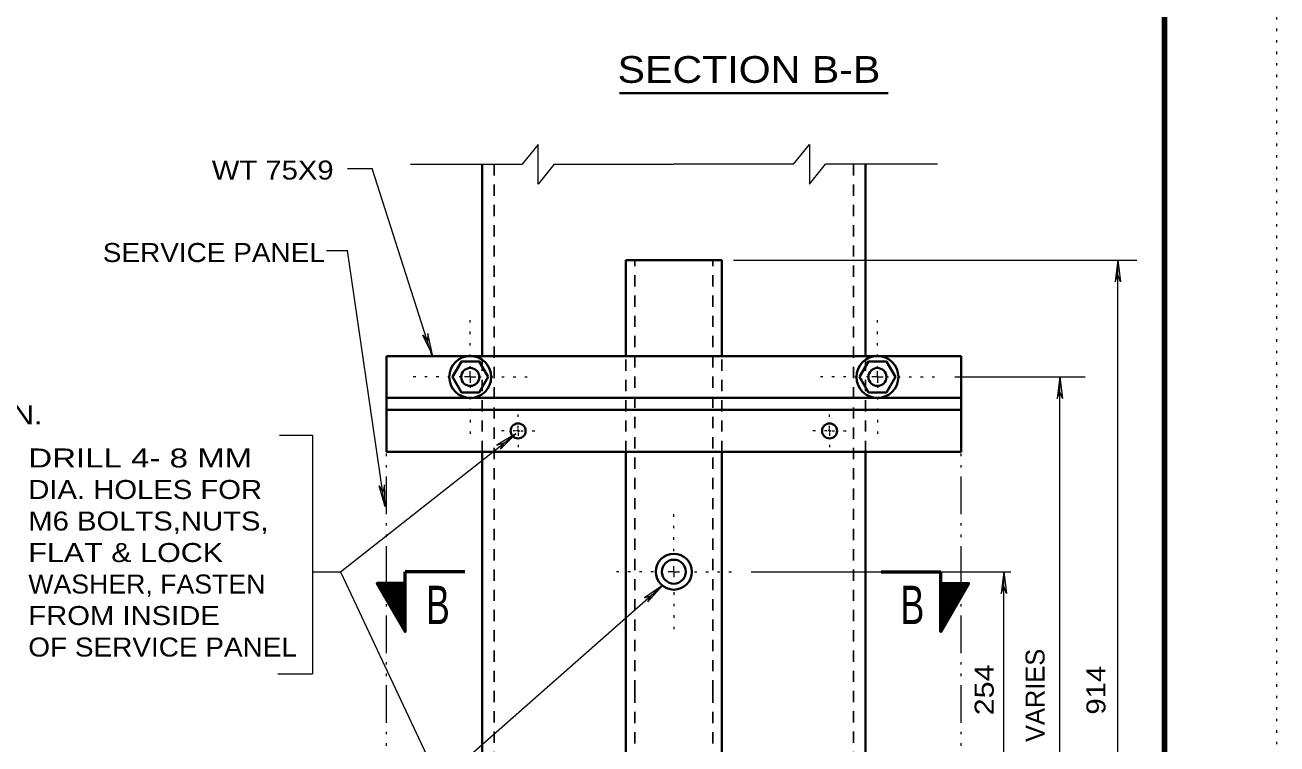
# Model space of a CAD drawing. Extents: x 312583 to 312854, y 144419 to 144597.
# Drawn here: x 312803.4 to 312853.5, y 144478.4 to 144507.1 of the extents above; entities that cross this region are included whole.
import ezdxf
from ezdxf.enums import TextEntityAlignment as Align

# ---------------------------------------------------------------- set-up
doc = ezdxf.new("R2010")
doc.units = 0
doc.header["$LTSCALE"] = 0.3
for name, pattern in [('DASH_DOUBLE_DOT', [9.2, 5, -1.2, 0.3, -1.2, 0.3, -1.2]), ('DOTTED', [1.5, 0.3, -1.2]), ('SHORT_DASHED', [2.7, 1.5, -1.2])]:
    doc.linetypes.add(name, pattern=pattern)
doc.layers.add('1', color=7, linetype='Continuous', lineweight=13)
doc.layers.add('63', color=7, linetype='DOTTED', lineweight=13)

msp = doc.modelspace()

# ---------------------------------------------------------------- linework, layer by layer
at = {"layer": '1', "lineweight": 158}
msp.add_line((312849, 144423.1446), (312849, 144585.0846), dxfattribs=at)
at = {"layer": '1', "lineweight": 35}
for p, q in [((312827.1926, 144504.4241), (312837.9474, 144504.4241)), ((312817.5353, 144484.8097), (312817.5199, 144484.7943)), ((312817.5813, 144484.8097), (312817.5276, 144484.7713)), ((312817.6349, 144484.8097), (312817.5429, 144484.756)), ((312817.6809, 144484.8097), (312817.5583, 144484.733)), ((312817.7346, 144484.8097), (312817.5659, 144484.71)), ((312817.7729, 144484.8097), (312817.5813, 144484.6947)), ((312817.8266, 144484.8097), (312817.5889, 144484.6717)), ((312817.8726, 144484.8097), (312817.6043, 144484.6487)), ((312817.9186, 144484.8097), (312817.6119, 144484.6333)), ((312817.9646, 144484.8097), (312817.6273, 144484.6027)), ((312818.0183, 144484.8097), (312817.6349, 144484.5873)), ((312818.0643, 144484.8097), (312817.6503, 144484.5643)), ((312818.1103, 144484.8097), (312817.6579, 144484.5413)), ((312818.1639, 144484.8097), (312817.6733, 144484.526)), ((312818.2099, 144484.8097), (312817.6809, 144484.503)), ((312818.2559, 144484.8097), (312817.6963, 144484.4877)), ((312818.3096, 144484.8097), (312817.7116, 144484.4647)), ((312818.3556, 144484.8097), (312817.7193, 144484.4417)), ((312818.4016, 144484.8097), (312817.7346, 144484.4263)), ((312818.4476, 144484.8097), (312817.7499, 144484.4033)), ((312818.5013, 144484.8097), (312817.7576, 144484.3803)), ((312818.5396, 144484.8097), (312817.7729, 144484.365)), ((312818.5933, 144484.8097), (312817.7806, 144484.3343)), ((312818.6163, 144484.7943), (312817.7959, 144484.319)), ((312818.6163, 144484.7637), (312817.8036, 144484.296)), ((312818.6163, 144484.733), (312817.8189, 144484.273)), ((312818.6163, 144484.71), (312817.8266, 144484.2577)), ((312818.6163, 144484.6793), (312817.8419, 144484.2347)), ((312818.6086, 144484.6563), (312817.8496, 144484.2117)), ((312818.6086, 144484.6257), (312817.8649, 144484.1963)), ((312818.6163, 144484.6027), (312817.8726, 144484.1733)), ((312818.6163, 144484.572), (312817.8879, 144484.1503)), ((312818.6163, 144484.5413), (312817.9033, 144484.135)), ((312818.6163, 144484.5183), (312817.9109, 144484.112)), ((312818.6163, 144484.4877), (312817.9263, 144484.089)), ((312818.6163, 144484.457), (312817.9416, 144484.066)), ((312818.6163, 144484.434), (312817.9493, 144484.0507)), ((312818.6086, 144484.4033), (312817.9646, 144484.0277)), ((312818.6163, 144484.3727), (312817.9723, 144484.0047)), ((312840.0523, 144484.7943), (312840.8726, 144484.319)), ((312840.0523, 144484.7637), (312840.8649, 144484.296)), ((312840.0523, 144484.733), (312840.8496, 144484.273)), ((312840.0523, 144484.71), (312840.8419, 144484.2577)), ((312840.0523, 144484.6793), (312840.8266, 144484.2347)), ((312840.0523, 144484.6027), (312840.7959, 144484.1733)), ((312840.0523, 144484.572), (312840.7806, 144484.1503)), ((312840.0523, 144484.5413), (312840.7653, 144484.135)), ((312840.0523, 144484.5183), (312840.7576, 144484.112)), ((312840.0523, 144484.4877), (312840.7423, 144484.089)), ((312840.0523, 144484.457), (312840.7269, 144484.066)), ((312840.0523, 144484.434), (312840.7193, 144484.0507)), ((312840.0523, 144484.3727), (312840.6963, 144484.0047)), ((312840.0599, 144484.6563), (312840.8189, 144484.2117)), ((312840.0599, 144484.6257), (312840.8036, 144484.1963)), ((312840.0599, 144484.4033), (312840.7039, 144484.0277)), ((312840.0753, 144484.8097), (312840.8879, 144484.3343)), ((312840.1289, 144484.8097), (312840.8956, 144484.365)), ((312840.1673, 144484.8097), (312840.9109, 144484.3803)), ((312840.2209, 144484.8097), (312840.9186, 144484.4033)), ((312840.2669, 144484.8097), (312840.9339, 144484.4263)), ((312840.3129, 144484.8097), (312840.9493, 144484.4417)), ((312840.3589, 144484.8097), (312840.9569, 144484.4647)), ((312840.4126, 144484.8097), (312840.9723, 144484.4877)), ((312840.4586, 144484.8097), (312840.9876, 144484.503)), ((312840.5046, 144484.8097), (312840.9953, 144484.526)), ((312840.5583, 144484.8097), (312841.0106, 144484.5413)), ((312840.6043, 144484.8097), (312841.0183, 144484.5643)), ((312840.6503, 144484.8097), (312841.0336, 144484.5873)), ((312840.7039, 144484.8097), (312841.0413, 144484.6027)), ((312840.7499, 144484.8097), (312841.0566, 144484.6333)), ((312840.7959, 144484.8097), (312841.0643, 144484.6487)), ((312840.8419, 144484.8097), (312841.0796, 144484.6717)), ((312840.8956, 144484.8097), (312841.0873, 144484.6947)), ((312840.9339, 144484.8097), (312841.1026, 144484.71)), ((312840.9876, 144484.8097), (312841.1103, 144484.733)), ((312841.0336, 144484.8097), (312841.1256, 144484.756)), ((312841.0873, 144484.8097), (312841.1409, 144484.7713)), ((312841.1333, 144484.8097), (312841.1486, 144484.7943)), ((312818.6163, 144484.3497), (312817.9876, 144483.9893)), ((312818.6163, 144484.3267), (312817.9953, 144483.9663)), ((312818.6163, 144484.296), (312818.0106, 144483.9433)), ((312818.6163, 144484.2653), (312818.0183, 144483.928)), ((312818.6163, 144484.2347), (312818.0336, 144483.905)), ((312818.6163, 144484.2117), (312818.0413, 144483.882)), ((312818.6163, 144484.181), (312818.0566, 144483.8667)), ((312818.6086, 144484.158), (312818.0643, 144483.836)), ((312818.6163, 144484.1273), (312818.0796, 144483.8207)), ((312818.6163, 144484.1043), (312818.0949, 144483.7977)), ((312818.6163, 144484.0737), (312818.1026, 144483.7747)), ((312818.6163, 144484.043), (312818.1179, 144483.7593)), ((312818.6163, 144484.02), (312818.1256, 144483.7363)), ((312818.6163, 144483.9893), (312818.1409, 144483.7133)), ((312818.6163, 144483.9587), (312818.1486, 144483.698)), ((312818.6163, 144483.9357), (312818.1639, 144483.675)), ((312818.6163, 144483.905), (312818.1716, 144483.652)), ((312818.6163, 144483.8743), (312818.1869, 144483.6367)), ((312840.0523, 144484.3497), (312840.6809, 144483.9893)), ((312840.0523, 144484.3267), (312840.6733, 144483.9663)), ((312840.0523, 144484.296), (312840.6579, 144483.9433)), ((312840.0523, 144484.2653), (312840.6503, 144483.928)), ((312840.0523, 144484.2347), (312840.6349, 144483.905)), ((312840.0523, 144484.2117), (312840.6273, 144483.882)), ((312840.0523, 144484.181), (312840.6119, 144483.8667)), ((312840.0523, 144484.1273), (312840.5889, 144483.8207)), ((312840.0523, 144484.1043), (312840.5736, 144483.7977)), ((312840.0523, 144484.0737), (312840.5659, 144483.7747)), ((312840.0523, 144484.043), (312840.5506, 144483.7593)), ((312840.0523, 144484.02), (312840.5429, 144483.7363)), ((312840.0523, 144483.9893), (312840.5276, 144483.7133)), ((312840.0523, 144483.9587), (312840.5199, 144483.698)), ((312840.0523, 144483.9357), (312840.5046, 144483.675)), ((312840.0523, 144483.905), (312840.4969, 144483.652)), ((312840.0523, 144483.8743), (312840.4816, 144483.6367)), ((312840.0599, 144484.158), (312840.6043, 144483.836)), ((312818.6163, 144483.8513), (312818.1946, 144483.6137)), ((312818.6163, 144483.8283), (312818.2099, 144483.5907)), ((312818.6163, 144483.7977), (312818.2176, 144483.5677)), ((312818.6163, 144483.767), (312818.2329, 144483.5523)), ((312818.6163, 144483.7363), (312818.2483, 144483.5293)), ((312818.6163, 144483.7133), (312818.2559, 144483.5063)), ((312818.6163, 144483.6827), (312818.2713, 144483.491)), ((312818.6163, 144483.6597), (312818.2866, 144483.468)), ((312818.6163, 144483.629), (312818.2943, 144483.445)), ((312818.6163, 144483.606), (312818.3096, 144483.4297)), ((312818.6163, 144483.5753), (312818.3173, 144483.4067)), ((312818.6163, 144483.5447), (312818.3326, 144483.3837)), ((312818.6163, 144483.5217), (312818.3403, 144483.3683)), ((312818.6163, 144483.491), (312818.3556, 144483.3377)), ((312818.6163, 144483.468), (312818.3633, 144483.3223)), ((312818.6163, 144483.4373), (312818.3786, 144483.2993)), ((312818.6163, 144483.4067), (312818.3863, 144483.2763)), ((312818.6163, 144483.3837), (312818.4016, 144483.261)), ((312840.0523, 144483.8513), (312840.4739, 144483.6137)), ((312840.0523, 144483.8283), (312840.4586, 144483.5907)), ((312840.0523, 144483.7977), (312840.4509, 144483.5677)), ((312840.0523, 144483.767), (312840.4356, 144483.5523)), ((312840.0523, 144483.7363), (312840.4203, 144483.5293)), ((312840.0523, 144483.7133), (312840.4126, 144483.5063)), ((312840.0523, 144483.6827), (312840.3973, 144483.491)), ((312840.0523, 144483.6597), (312840.3819, 144483.468)), ((312840.0523, 144483.629), (312840.3743, 144483.445)), ((312840.0523, 144483.606), (312840.3589, 144483.4297)), ((312840.0523, 144483.5753), (312840.3513, 144483.4067)), ((312840.0523, 144483.5447), (312840.3359, 144483.3837)), ((312840.0523, 144483.5217), (312840.3283, 144483.3683)), ((312840.0523, 144483.491), (312840.3129, 144483.3377)), ((312840.0523, 144483.468), (312840.3053, 144483.3223)), ((312840.0523, 144483.4373), (312840.2899, 144483.2993)), ((312840.0523, 144483.4067), (312840.2823, 144483.2763)), ((312840.0523, 144483.3837), (312840.2669, 144483.261)), ((312818.6163, 144483.353), (312818.4093, 144483.238)), ((312818.6163, 144483.33), (312818.4246, 144483.215)), ((312818.6163, 144483.2993), (312818.4399, 144483.1997)), ((312818.6163, 144483.2687), (312818.4476, 144483.1767)), ((312818.6163, 144483.238), (312818.4629, 144483.1537)), ((312818.6163, 144483.215), (312818.4783, 144483.1383)), ((312818.6163, 144483.1843), (312818.4859, 144483.1153)), ((312818.6163, 144483.1613), (312818.5013, 144483.0923)), ((312818.6163, 144483.1383), (312818.5089, 144483.0693)), ((312818.6163, 144483.1077), (312818.5243, 144483.054)), ((312818.6163, 144483.077), (312818.5319, 144483.031)), ((312818.6163, 144483.0463), (312818.5473, 144483.008)), ((312818.6163, 144483.0233), (312818.5549, 144482.9927)), ((312818.6163, 144482.9927), (312818.5703, 144482.9697)), ((312818.6163, 144482.9697), (312818.5779, 144482.9467)), ((312818.6163, 144482.939), (312818.5933, 144482.9313)), ((312818.6163, 144482.9083), (312818.6009, 144482.9083)), ((312840.0523, 144483.353), (312840.2593, 144483.238)), ((312840.0523, 144483.33), (312840.2439, 144483.215)), ((312840.0523, 144483.2993), (312840.2286, 144483.1997)), ((312840.0523, 144483.2687), (312840.2209, 144483.1767)), ((312840.0523, 144483.238), (312840.2056, 144483.1537)), ((312840.0523, 144483.215), (312840.1903, 144483.1383)), ((312840.0523, 144483.1843), (312840.1826, 144483.1153)), ((312840.0523, 144483.1613), (312840.1673, 144483.0923)), ((312840.0523, 144483.1383), (312840.1596, 144483.0693)), ((312840.0523, 144483.1077), (312840.1443, 144483.054)), ((312840.0523, 144483.077), (312840.1366, 144483.031)), ((312840.0523, 144483.0463), (312840.1213, 144483.008)), ((312840.0523, 144483.0233), (312840.1136, 144482.9927)), ((312840.0523, 144482.9927), (312840.0983, 144482.9697)), ((312840.0523, 144482.9697), (312840.0906, 144482.9467)), ((312840.0523, 144482.939), (312840.0753, 144482.9313)), ((312840.0523, 144482.9083), (312840.0676, 144482.9083))]:
    msp.add_line(p, q, dxfattribs=at)
at = {"layer": '1'}
for p, q in [((312816.3208, 144501.4089), (312817.3027, 144501.4089)), ((312819.6973, 144493.91), (312817.3027, 144501.4089)), ((312818.8309, 144501.5767), (312823.3006, 144501.5767)), ((312824.5809, 144501.5767), (312829.3726, 144501.5767)), ((312834.1643, 144501.5767), (312829.3726, 144501.5767)), ((312839.9143, 144501.5767), (312835.4446, 144501.5767)), ((312815.4739, 144498.1279), (312816.3206, 144498.1279)), ((312817.8036, 144487.8993), (312816.3206, 144498.1279)), ((312847.1303, 144497.7433), (312847.023, 144496.877)), ((312847.1303, 144463.2433), (312847.1303, 144497.7433)), ((312847.1303, 144497.7433), (312847.2377, 144496.877)), ((312847.023, 144496.877), (312847.1303, 144497.153)), ((312847.2377, 144496.877), (312847.1303, 144497.153)), ((312819.3273, 144494.7409), (312819.5192, 144494.517)), ((312819.7101, 144493.9556), (312819.3273, 144494.7409)), ((312819.5277, 144494.8103), (312819.5192, 144494.517)), ((312819.7101, 144493.9556), (312819.5277, 144494.8103)), ((312821.2229, 144493.0743), (312821.0006, 144493.0743)), ((312821.2229, 144493.0743), (312821.2229, 144493.3043)), ((312821.2229, 144493.0743), (312821.4529, 144493.0743)), ((312821.2229, 144493.0743), (312821.2229, 144492.8443)), ((312837.5146, 144493.0743), (312837.2923, 144493.0743)), ((312837.5146, 144493.0743), (312837.5146, 144493.3043)), ((312837.5146, 144493.0743), (312837.5146, 144492.8443)), ((312837.5146, 144493.0743), (312837.7446, 144493.0743)), ((312844.8088, 144493.0743), (312844.7015, 144492.208)), ((312844.8088, 144467.92), (312844.8088, 144493.0743)), ((312844.8088, 144493.0743), (312844.9162, 144492.208)), ((312844.7015, 144492.208), (312844.8088, 144492.484)), ((312844.9162, 144492.208), (312844.8088, 144492.484)), ((312823.1396, 144490.92), (312823.0783, 144490.92)), ((312823.1396, 144490.92), (312823.1396, 144490.9813)), ((312823.1396, 144490.92), (312823.2086, 144490.92)), ((312823.1396, 144490.92), (312823.1396, 144490.851)), ((312835.5979, 144490.92), (312835.5366, 144490.92)), ((312835.5979, 144490.92), (312835.5979, 144490.9813)), ((312835.5979, 144490.92), (312835.5979, 144490.851)), ((312835.5979, 144490.92), (312835.6669, 144490.92)), ((312813.5981, 144490.7483), (312814.9182, 144490.7483)), ((312814.9182, 144490.7483), (312814.9169, 144481.2029)), ((312823.0476, 144490.805), (312822.2963, 144490.3527)), ((312822.2963, 144490.3527), (312822.5799, 144490.437)), ((312823.0476, 144490.805), (312822.4343, 144490.184)), ((312822.4343, 144490.184), (312822.5799, 144490.437)), ((312817.5767, 144488.7268), (312817.7255, 144488.4722)), ((312817.817, 144487.8922), (312817.5767, 144488.7268)), ((312817.7903, 144488.7658), (312817.7255, 144488.4722)), ((312817.817, 144487.8922), (312817.7903, 144488.7658)), ((312829.3726, 144485.285), (312829.3726, 144485.515)), ((312816.0403, 144485.285), (312823.1166, 144470.22)), ((312829.3726, 144485.285), (312829.1426, 144485.285)), ((312829.3726, 144485.285), (312829.6026, 144485.285)), ((312829.3726, 144485.285), (312829.3726, 144485.0627)), ((312832.4623, 144485.285), (312841.6875, 144485.285)), ((312841.6875, 144485.285), (312842.8551, 144485.285)), ((312842.5782, 144485.285), (312842.4709, 144484.4187)), ((312842.5782, 144475.7017), (312842.5782, 144485.285)), ((312842.5782, 144485.285), (312842.6856, 144484.4187)), ((312820.3183, 144477.166), (312828.9203, 144484.733)), ((312828.9203, 144484.733), (312828.1919, 144484.2423)), ((312828.9203, 144484.733), (312828.3376, 144484.0813)), ((312842.4709, 144484.4187), (312842.5782, 144484.6947)), ((312842.6856, 144484.4187), (312842.5782, 144484.6947)), ((312828.1919, 144484.2423), (312828.4756, 144484.342)), ((312828.3376, 144484.0813), (312828.4756, 144484.342)), ((312813.528, 144481.2029), (312814.9169, 144481.2029))]:
    msp.add_line(p, q, dxfattribs=at)
at = {"layer": '1', "lineweight": 40}
for p, q in [((312821.7059, 144493.91), (312821.7059, 144501.5767)), ((312837.0393, 144493.91), (312837.0393, 144501.5767)), ((312827.4559, 144497.7433), (312829.3726, 144497.7433)), ((312827.4559, 144493.91), (312827.4559, 144497.7433)), ((312831.2893, 144497.7433), (312829.3726, 144497.7433)), ((312831.2893, 144493.91), (312831.2893, 144497.7433)), ((312817.8726, 144493.91), (312829.3726, 144493.91)), ((312817.8726, 144490.0767), (312817.8726, 144493.91)), ((312840.8726, 144493.91), (312829.3726, 144493.91)), ((312840.8726, 144490.0767), (312840.8726, 144493.91)), ((312817.8726, 144492.2387), (312829.3726, 144492.2387)), ((312840.8726, 144492.2387), (312829.3726, 144492.2387)), ((312817.8726, 144491.7557), (312829.3726, 144491.7557)), ((312840.8726, 144491.7557), (312829.3726, 144491.7557)), ((312817.8726, 144490.0767), (312829.3726, 144490.0767)), ((312821.7059, 144480.4933), (312821.7059, 144490.0767)), ((312827.4559, 144480.4933), (312827.4559, 144490.0767)), ((312840.8726, 144490.0767), (312829.3726, 144490.0767)), ((312831.2893, 144480.4933), (312831.2893, 144490.0767)), ((312837.0393, 144480.4933), (312837.0393, 144490.0767)), ((312821.7059, 144480.4933), (312821.7059, 144470.91)), ((312827.4559, 144480.4933), (312827.4559, 144470.91)), ((312831.2893, 144480.4933), (312831.2893, 144470.91)), ((312837.0393, 144480.4933), (312837.0393, 144470.91))]:
    msp.add_line(p, q, dxfattribs=at)
at = {"layer": '1', "linetype": 'SHORT_DASHED', "lineweight": 25}
for p, q in [((312822.1813, 144501.5767), (312822.1813, 144459.41)), ((312836.5563, 144501.5767), (312836.5563, 144459.41)), ((312827.8163, 144480.4933), (312827.8163, 144497.7433)), ((312830.9289, 144480.4933), (312830.9289, 144497.7433)), ((312821.7059, 144490.0767), (312821.7059, 144493.91)), ((312827.4559, 144490.0767), (312827.4559, 144493.91)), ((312831.2893, 144490.0767), (312831.2893, 144493.91)), ((312837.0393, 144490.0767), (312837.0393, 144493.91)), ((312827.8163, 144480.4933), (312827.8163, 144463.2433)), ((312830.9289, 144480.4933), (312830.9289, 144463.2433))]:
    msp.add_line(p, q, dxfattribs=at)
at = {"layer": '1', "linetype": 'DOTTED'}
for p, q in [((312821.2229, 144493.4117), (312821.2229, 144495.6887)), ((312837.5146, 144493.4117), (312837.5146, 144495.6887)), ((312820.8856, 144493.0743), (312818.6163, 144493.0743)), ((312821.5679, 144493.0743), (312823.8373, 144493.0743)), ((312837.1773, 144493.0743), (312834.9079, 144493.0743)), ((312837.8596, 144493.0743), (312840.1289, 144493.0743)), ((312821.2229, 144492.737), (312821.2229, 144490.46)), ((312837.5146, 144492.737), (312837.5146, 144490.46)), ((312823.1396, 144491.0197), (312823.1396, 144491.6943)), ((312835.5979, 144491.0197), (312835.5979, 144491.6943)), ((312823.0399, 144490.92), (312822.3653, 144490.92)), ((312823.2469, 144490.92), (312823.9139, 144490.92)), ((312835.4983, 144490.92), (312834.8236, 144490.92)), ((312835.7053, 144490.92), (312836.3723, 144490.92)), ((312823.1396, 144490.8203), (312823.1396, 144490.1457)), ((312835.5979, 144490.8203), (312835.5979, 144490.1457)), ((312829.3726, 144486.1053), (312829.3726, 144487.8993)), ((312828.5523, 144485.285), (312826.7583, 144485.285)), ((312830.1929, 144485.285), (312831.9869, 144485.285)), ((312829.3726, 144484.4647), (312829.3726, 144482.6707))]:
    msp.add_line(p, q, dxfattribs=at)
at = {"layer": '1', "linetype": 'DASH_DOUBLE_DOT'}
for p, q in [((312817.8726, 144470.91), (312817.8726, 144490.0767)), ((312840.8726, 144470.91), (312840.8726, 144490.0767))]:
    msp.add_line(p, q, dxfattribs=at)
at = {"layer": '1', "lineweight": 53}
for p, q in [((312821.0083, 144485.285), (312818.6163, 144485.285)), ((312818.6163, 144484.8097), (312818.6163, 144485.285)), ((312837.6603, 144485.285), (312840.0523, 144485.285)), ((312840.0523, 144484.8097), (312840.0523, 144485.285))]:
    msp.add_line(p, q, dxfattribs=at)
at = {"layer": '1'}
for points in [[(312824.5809, 144501.5767), (312823.9446, 144500.7793), (312823.9446, 144502.374), (312823.3006, 144501.5767)], [(312834.1643, 144501.5767), (312834.8006, 144502.374), (312834.8006, 144500.7793), (312835.4446, 144501.5767)], [(312831.7646, 144497.7433), (312842.8551, 144497.7433), (312847.8922, 144497.7433)], [(312840.6119, 144493.0743), (312842.8551, 144493.0743), (312845.8225, 144493.0743)], [(312814.9169, 144485.285), (312816.0403, 144485.285), (312823.0476, 144490.805)]]:
    msp.add_lwpolyline(points, dxfattribs=at)
at = {"layer": '1', "lineweight": 40}
for points in [[(312821.9436, 144493.0743), (312821.5833, 144492.4533), (312820.8703, 144492.4533), (312820.5099, 144493.0743), (312820.8703, 144493.6953), (312821.5833, 144493.6953)], [(312836.8016, 144493.0743), (312837.1619, 144492.4533), (312837.8749, 144492.4533), (312838.2353, 144493.0743), (312837.8749, 144493.6953), (312837.1619, 144493.6953)]]:
    msp.add_lwpolyline(points, close=True, dxfattribs=at)
at = {"layer": '1', "lineweight": 53}
for points in [[(312818.6163, 144484.8097), (312817.5046, 144484.8097), (312818.6163, 144482.893)], [(312840.0523, 144484.8097), (312841.1639, 144484.8097), (312840.0523, 144482.893)]]:
    msp.add_lwpolyline(points, close=True, dxfattribs=at)
at = {"layer": '1', "lineweight": 40}
for centre, radius in [((312821.2258, 144493.0734), 0.8385), ((312837.5175, 144493.0734), 0.8385), ((312821.2258, 144493.0734), 0.3594), ((312837.5175, 144493.0734), 0.3594), ((312823.1425, 144490.9171), 0.2995), ((312835.6008, 144490.9171), 0.2995), ((312829.3716, 144485.2869), 0.7188), ((312829.3716, 144485.2869), 0.4792)]:
    msp.add_circle(centre, radius, dxfattribs=at)
at = {"layer": '63'}
msp.add_lwpolyline([(312601.2, 144418.5846), (312853.5, 144418.5846), (312853.5, 144596.7846)], dxfattribs=at)

# ---------------------------------------------------------------- texts
at = {"layer": '1'}
for s, height, width, p in [('SECTION B-B', 1.07, 1.15, (312832.3771, 144504.835)), ('B', 1.533, 0.7, (312819.9311, 144483.192)), ('B', 1.533, 0.7, (312838.9138, 144483.192))]:
    msp.add_text(s, height=height, dxfattribs=dict(at, width=width)).set_placement(p, align=Align.CENTER)
for s, width, p in [('WT 75X9', 1.15, (312810.8885, 144500.9672)), ('SERVICE PANEL', 1.1, (312806.5262, 144497.6695)), ('76 MIN.', 1.2, (312799.8425, 144491.1768)), ('DRILL 4- 8 MM ', 1.3, (312803.5458, 144489.4538)), ('DIA. HOLES FOR', 1.15, (312803.5458, 144488.1938)), ('M6 BOLTS,NUTS,', 1.15, (312803.5458, 144486.9338)), ('FLAT & LOCK', 1.2, (312803.5458, 144485.6738)), ('WASHER, FASTEN', 1.05, (312803.5458, 144484.4138)), ('FROM INSIDE ', 1.15, (312803.5458, 144483.1538)), ('OF SERVICE PANEL', 1.1, (312803.5458, 144481.8938))]:
    msp.add_text(s, height=0.76, dxfattribs=dict(at, width=width)).set_placement(p)
msp.add_text('VARIES', height=0.76, rotation=90, dxfattribs=at).set_placement((312844.2026, 144478.4782))
for s, width, p in [('254 ', 1.2, (312842.167, 144479.5437)), ('914 ', 1.15, (312846.6385, 144479.5734))]:
    msp.add_text(s, height=0.76, rotation=90, dxfattribs=dict(at, width=width)).set_placement(p)

doc.saveas('drawing.dxf')
